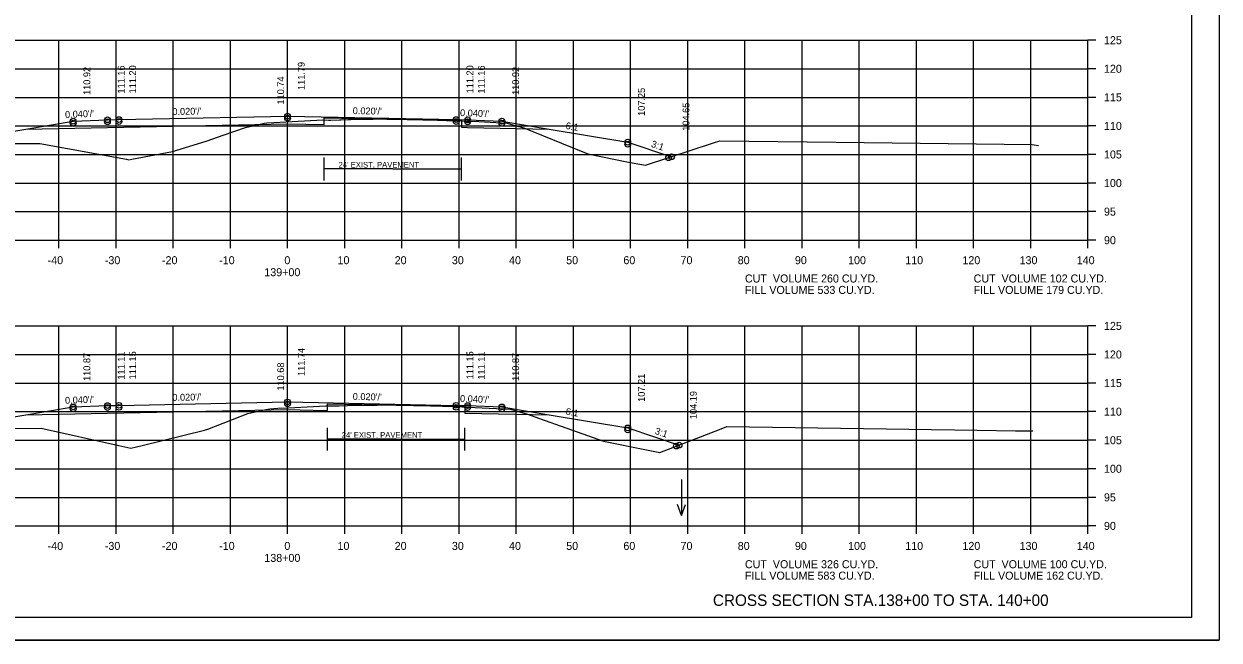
# Model space of a CAD drawing. Extents: x 1175611 to 1176402, y -433344 to -416213.
# Drawn here: x 1175734.9 to 1175943.9, y -430143.5 to -430035.6 of the extents above; entities that cross this region are included whole.
import ezdxf

# ---------------------------------------------------------------- set-up
doc = ezdxf.new("R2010")
doc.units = 0
for name, color, linetype in [('Default', 7, 'Continuous'), ('R_Alt Surface', 7, 'Continuous'), ('R_Axis', 7, 'Continuous'), ('R_Axis Annot', 7, 'Continuous'), ('R_Border', 7, 'Continuous'), ('R_Draft', 7, 'Continuous'), ('R_Exist Surface', 7, 'Continuous'), ('R_Fin Surface', 7, 'Continuous'), ('R_Grid', 7, 'Continuous'), ('R_No Plot', 7, 'Continuous'), ('R_Water Annot', 7, 'Continuous'), ('R_Xsect Elev', 7, 'Continuous'), ('R_Xsect Slope', 7, 'Continuous')]:
    doc.layers.add(name, color=color, linetype=linetype)

msp = doc.modelspace()

# ---------------------------------------------------------------- linework, layer by layer
at = {"layer": 'R_Alt Surface'}
for points in [[(1175735.2, -430054.03), (1175749.47, -430053.74), (1175780.97, -430053.11), (1175787.4, -430053.24), (1175787.4, -430052.07), (1175811.4, -430052.55), (1175811.4, -430053.72), (1175812.47, -430053.74), (1175826.75, -430054.03)], [(1175735.2, -430104.04), (1175749.47, -430103.76), (1175780.97, -430103.12), (1175787.65, -430103.26), (1175787.94, -430103.26), (1175787.94, -430102.1), (1175811.95, -430102.58), (1175811.95, -430103.74), (1175826.75, -430104.04)]]:
    msp.add_lwpolyline(points, dxfattribs=at)
at = {"layer": 'R_Axis'}
for p, q in [((1175920.97, -430073.48), (1175920.97, -430038.48)), ((1175922.37, -430038.48), (1175920.97, -430038.48)), ((1175922.37, -430043.48), (1175920.97, -430043.48)), ((1175922.37, -430048.48), (1175920.97, -430048.48)), ((1175922.37, -430053.48), (1175920.97, -430053.48)), ((1175922.37, -430058.48), (1175920.97, -430058.48)), ((1175922.37, -430063.48), (1175920.97, -430063.48)), ((1175922.37, -430068.48), (1175920.97, -430068.48)), ((1175640.97, -430073.48), (1175920.97, -430073.48)), ((1175740.97, -430074.88), (1175740.97, -430073.48)), ((1175750.97, -430074.88), (1175750.97, -430073.48)), ((1175760.97, -430074.88), (1175760.97, -430073.48)), ((1175770.97, -430074.88), (1175770.97, -430073.48)), ((1175780.97, -430074.88), (1175780.97, -430073.48)), ((1175790.97, -430074.88), (1175790.97, -430073.48)), ((1175800.97, -430074.88), (1175800.97, -430073.48)), ((1175810.97, -430074.88), (1175810.97, -430073.48)), ((1175820.97, -430074.88), (1175820.97, -430073.48)), ((1175830.97, -430074.88), (1175830.97, -430073.48)), ((1175840.97, -430074.88), (1175840.97, -430073.48)), ((1175850.97, -430074.88), (1175850.97, -430073.48)), ((1175860.97, -430074.88), (1175860.97, -430073.48)), ((1175870.97, -430074.88), (1175870.97, -430073.48)), ((1175880.97, -430074.88), (1175880.97, -430073.48)), ((1175890.97, -430074.88), (1175890.97, -430073.48)), ((1175900.97, -430074.88), (1175900.97, -430073.48)), ((1175910.97, -430074.88), (1175910.97, -430073.48)), ((1175920.97, -430074.88), (1175920.97, -430073.48)), ((1175922.37, -430073.48), (1175920.97, -430073.48)), ((1175920.97, -430123.48), (1175920.97, -430088.48)), ((1175922.37, -430088.48), (1175920.97, -430088.48)), ((1175922.37, -430093.48), (1175920.97, -430093.48)), ((1175922.37, -430098.48), (1175920.97, -430098.48)), ((1175922.37, -430103.48), (1175920.97, -430103.48)), ((1175922.37, -430108.48), (1175920.97, -430108.48)), ((1175922.37, -430113.48), (1175920.97, -430113.48)), ((1175922.37, -430118.48), (1175920.97, -430118.48)), ((1175640.97, -430123.48), (1175920.97, -430123.48)), ((1175740.97, -430124.88), (1175740.97, -430123.48)), ((1175750.97, -430124.88), (1175750.97, -430123.48)), ((1175760.97, -430124.88), (1175760.97, -430123.48)), ((1175770.97, -430124.88), (1175770.97, -430123.48)), ((1175780.97, -430124.88), (1175780.97, -430123.48)), ((1175790.97, -430124.88), (1175790.97, -430123.48)), ((1175800.97, -430124.88), (1175800.97, -430123.48)), ((1175810.97, -430124.88), (1175810.97, -430123.48)), ((1175820.97, -430124.88), (1175820.97, -430123.48)), ((1175830.97, -430124.88), (1175830.97, -430123.48)), ((1175840.97, -430124.88), (1175840.97, -430123.48)), ((1175850.97, -430124.88), (1175850.97, -430123.48)), ((1175860.97, -430124.88), (1175860.97, -430123.48)), ((1175870.97, -430124.88), (1175870.97, -430123.48)), ((1175880.97, -430124.88), (1175880.97, -430123.48)), ((1175890.97, -430124.88), (1175890.97, -430123.48)), ((1175900.97, -430124.88), (1175900.97, -430123.48)), ((1175910.97, -430124.88), (1175910.97, -430123.48)), ((1175920.97, -430124.88), (1175920.97, -430123.48)), ((1175922.37, -430123.48), (1175920.97, -430123.48))]:
    msp.add_line(p, q, dxfattribs=at)
at = {"layer": 'R_Border'}
for q in [(1175939.15, -429934.02), (1175622.97, -430139.48)]:
    msp.add_line((1175939.15, -430139.48), q, dxfattribs=at)
at = {"layer": 'R_Draft'}
for p, q in [((1175799.4, -430061.01), (1175787.4, -430061.01)), ((1175799.4, -430061.01), (1175811.4, -430061.01)), ((1175799.94, -430108.29), (1175787.94, -430108.29)), ((1175799.94, -430108.29), (1175811.95, -430108.29))]:
    msp.add_line(p, q, dxfattribs=at)
for points in [[(1175787.4, -430063.01), (1175787.4, -430059.01)], [(1175811.4, -430063.01), (1175811.4, -430059.01)], [(1175787.94, -430110.29), (1175787.94, -430106.29)], [(1175811.95, -430110.29), (1175811.95, -430106.29)]]:
    msp.add_lwpolyline(points, dxfattribs=at)
at = {"layer": 'R_Exist Surface'}
for points in [[(1175731.19, -430056.55), (1175737.66, -430056.53), (1175752.83, -430059.31), (1175753.22, -430059.39), (1175753.71, -430059.29), (1175760.87, -430057.93), (1175765.22, -430056.64), (1175766.91, -430056.09), (1175769.72, -430055.12), (1175773.63, -430053.76), (1175776.17, -430053.18), (1175776.88, -430053.02), (1175777.36, -430052.92), (1175778.55, -430052.86), (1175779.64, -430052.8), (1175787.14, -430052.43), (1175788.13, -430052.47), (1175788.35, -430052.48), (1175788.57, -430052.47), (1175790.08, -430052.42), (1175790.27, -430052.41), (1175791.62, -430052.38), (1175792.06, -430052.37), (1175795.61, -430052.32), (1175795.95, -430052.31), (1175796.96, -430052.26), (1175797.15, -430052.26), (1175798.33, -430052.27), (1175798.51, -430052.28), (1175799.87, -430052.3), (1175800.18, -430052.3), (1175801.87, -430052.35), (1175802.24, -430052.36), (1175804.61, -430052.4), (1175805.55, -430052.42), (1175808.78, -430052.51), (1175809.75, -430052.53), (1175809.87, -430052.53), (1175814.4, -430052.73), (1175819.4, -430052.97), (1175820.95, -430053.44), (1175822.29, -430053.83), (1175828.87, -430056.49), (1175833.48, -430058.35), (1175840.62, -430059.8), (1175843.6, -430060.37), (1175855.47, -430056.44), (1175856.58, -430056.09), (1175876.95, -430056.33), (1175911.23, -430056.75), (1175911.58, -430056.79), (1175912.33, -430056.91)], [(1175726.19, -430106.47), (1175737.86, -430106.39), (1175751.45, -430109.41), (1175753.55, -430109.87), (1175755.53, -430109.41), (1175766.47, -430106.75), (1175767.05, -430106.52), (1175774.03, -430103.8), (1175777.18, -430103.13), (1175777.87, -430102.97), (1175779.29, -430102.9), (1175781.15, -430102.8), (1175787.65, -430102.44), (1175788.32, -430102.46), (1175789.13, -430102.48), (1175790.01, -430102.45), (1175791.44, -430102.41), (1175794.27, -430102.36), (1175796.63, -430102.32), (1175797.31, -430102.3), (1175798.03, -430102.27), (1175798.54, -430102.28), (1175799.02, -430102.3), (1175800.15, -430102.32), (1175801.23, -430102.35), (1175804.21, -430102.41), (1175807.03, -430102.47), (1175808.09, -430102.5), (1175809.43, -430102.54), (1175810, -430102.55), (1175810.41, -430102.56), (1175813.8, -430102.73), (1175819.95, -430103.05), (1175821.16, -430103.4), (1175822.95, -430103.9), (1175825.04, -430104.66), (1175836.24, -430108.66), (1175843.73, -430110.16), (1175846.1, -430110.63), (1175856.51, -430106.58), (1175857.79, -430106.1), (1175901.61, -430106.75), (1175908.31, -430106.83), (1175908.71, -430106.83), (1175911.32, -430106.83)]]:
    msp.add_lwpolyline(points, dxfattribs=at)
at = {"layer": 'R_Fin Surface'}
for points in [[(1175694.36, -430056.6), (1175707.49, -430060.98), (1175721.47, -430056.32), (1175735.2, -430054.03), (1175743.47, -430052.65), (1175749.47, -430052.41), (1175751.47, -430052.37), (1175780.97, -430051.78), (1175810.47, -430052.37), (1175812.47, -430052.41), (1175818.47, -430052.65), (1175826.75, -430054.03), (1175840.47, -430056.32), (1175848.14, -430058.87)], [(1175694.36, -430056.6), (1175707.49, -430060.98), (1175721.47, -430056.32), (1175735.2, -430054.03), (1175743.47, -430052.65), (1175749.47, -430052.41), (1175751.47, -430052.37), (1175780.97, -430051.78), (1175810.47, -430052.37), (1175812.47, -430052.41), (1175818.47, -430052.65), (1175826.75, -430054.03), (1175840.47, -430056.32), (1175848.14, -430058.87)], [(1175690.65, -430106.73), (1175705.46, -430111.67), (1175721.47, -430106.33), (1175735.2, -430104.04), (1175743.47, -430102.66), (1175749.47, -430102.42), (1175751.47, -430102.38), (1175780.97, -430101.79), (1175810.47, -430102.38), (1175812.47, -430102.42), (1175818.47, -430102.66), (1175826.75, -430104.04), (1175840.47, -430106.33), (1175849.46, -430109.33)], [(1175690.65, -430106.73), (1175705.46, -430111.67), (1175721.47, -430106.33), (1175735.2, -430104.04), (1175743.47, -430102.66), (1175749.47, -430102.42), (1175751.47, -430102.38), (1175780.97, -430101.79), (1175810.47, -430102.38), (1175812.47, -430102.42), (1175818.47, -430102.66), (1175826.75, -430104.04), (1175840.47, -430106.33), (1175849.46, -430109.33)]]:
    msp.add_lwpolyline(points, dxfattribs=at)
at = {"layer": 'R_Grid'}
for p, q in [((1175640.97, -430038.48), (1175920.97, -430038.48)), ((1175740.97, -430073.48), (1175740.97, -430038.48)), ((1175750.97, -430073.48), (1175750.97, -430038.48)), ((1175760.97, -430073.48), (1175760.97, -430038.48)), ((1175770.97, -430073.48), (1175770.97, -430038.48)), ((1175780.97, -430073.48), (1175780.97, -430038.48)), ((1175790.97, -430073.48), (1175790.97, -430038.48)), ((1175800.97, -430073.48), (1175800.97, -430038.48)), ((1175810.97, -430073.48), (1175810.97, -430038.48)), ((1175820.97, -430073.48), (1175820.97, -430038.48)), ((1175830.97, -430073.48), (1175830.97, -430038.48)), ((1175840.97, -430073.48), (1175840.97, -430038.48)), ((1175850.97, -430073.48), (1175850.97, -430038.48)), ((1175860.97, -430073.48), (1175860.97, -430038.48)), ((1175870.97, -430073.48), (1175870.97, -430038.48)), ((1175880.97, -430073.48), (1175880.97, -430038.48)), ((1175890.97, -430073.48), (1175890.97, -430038.48)), ((1175900.97, -430073.48), (1175900.97, -430038.48)), ((1175910.97, -430073.48), (1175910.97, -430038.48)), ((1175920.97, -430073.48), (1175920.97, -430038.48)), ((1175640.97, -430043.48), (1175920.97, -430043.48)), ((1175640.97, -430048.48), (1175920.97, -430048.48)), ((1175640.97, -430053.48), (1175920.97, -430053.48)), ((1175640.97, -430058.48), (1175920.97, -430058.48)), ((1175640.97, -430063.48), (1175920.97, -430063.48)), ((1175640.97, -430068.48), (1175920.97, -430068.48)), ((1175640.97, -430073.48), (1175920.97, -430073.48)), ((1175640.97, -430088.48), (1175920.97, -430088.48)), ((1175740.97, -430123.48), (1175740.97, -430088.48)), ((1175750.97, -430123.48), (1175750.97, -430088.48)), ((1175760.97, -430123.48), (1175760.97, -430088.48)), ((1175770.97, -430123.48), (1175770.97, -430088.48)), ((1175780.97, -430123.48), (1175780.97, -430088.48)), ((1175790.97, -430123.48), (1175790.97, -430088.48)), ((1175800.97, -430123.48), (1175800.97, -430088.48)), ((1175810.97, -430123.48), (1175810.97, -430088.48)), ((1175820.97, -430123.48), (1175820.97, -430088.48)), ((1175830.97, -430123.48), (1175830.97, -430088.48)), ((1175840.97, -430123.48), (1175840.97, -430088.48)), ((1175850.97, -430123.48), (1175850.97, -430088.48)), ((1175860.97, -430123.48), (1175860.97, -430088.48)), ((1175870.97, -430123.48), (1175870.97, -430088.48)), ((1175880.97, -430123.48), (1175880.97, -430088.48)), ((1175890.97, -430123.48), (1175890.97, -430088.48)), ((1175900.97, -430123.48), (1175900.97, -430088.48)), ((1175910.97, -430123.48), (1175910.97, -430088.48)), ((1175920.97, -430123.48), (1175920.97, -430088.48)), ((1175640.97, -430093.48), (1175920.97, -430093.48)), ((1175640.97, -430098.48), (1175920.97, -430098.48)), ((1175640.97, -430103.48), (1175920.97, -430103.48)), ((1175640.97, -430108.48), (1175920.97, -430108.48)), ((1175640.97, -430113.48), (1175920.97, -430113.48)), ((1175640.97, -430118.48), (1175920.97, -430118.48)), ((1175640.97, -430123.48), (1175920.97, -430123.48))]:
    msp.add_line(p, q, dxfattribs=at)
at = {"layer": 'R_No Plot'}
msp.add_line((1175610.57, -430143.46), (1175943.91, -430143.46), dxfattribs=at)
msp.add_lwpolyline([(1175610.57, -429930.13), (1175943.91, -429930.13), (1175943.91, -430143.46), (1175610.57, -430143.46)], close=True, dxfattribs=at)
for centre in [(1175743.47, -430052.65), (1175749.47, -430052.41), (1175749.47, -430052.76), (1175751.47, -430052.37), (1175751.47, -430052.72), (1175780.97, -430051.78), (1175780.97, -430052.13), (1175810.47, -430052.37), (1175810.47, -430052.72), (1175812.47, -430052.41), (1175812.47, -430052.76), (1175818.47, -430052.65), (1175743.47, -430053), (1175818.47, -430053), (1175840.47, -430056.32), (1175840.47, -430056.67), (1175847.61, -430059.05), (1175848.14, -430058.87), (1175848.14, -430058.87), (1175743.47, -430102.66), (1175749.47, -430102.42), (1175749.47, -430102.77), (1175751.47, -430102.38), (1175751.47, -430102.73), (1175780.97, -430101.79), (1175780.97, -430102.14), (1175810.47, -430102.38), (1175810.47, -430102.73), (1175812.47, -430102.42), (1175812.47, -430102.77), (1175818.47, -430102.66), (1175743.47, -430103.01), (1175818.47, -430103.01), (1175840.47, -430106.33), (1175840.47, -430106.68), (1175848.97, -430109.51), (1175849.46, -430109.33), (1175849.46, -430109.33)]:
    msp.add_circle(centre, 0.5, dxfattribs=at)
at = {"layer": 'R_Water Annot'}
for p, q in [((1175849.85, -430115.35), (1175849.85, -430121.63)), ((1175849.85, -430121.63), (1175849.15, -430119.71)), ((1175849.85, -430121.63), (1175850.55, -430119.71))]:
    msp.add_line(p, q, dxfattribs=at)

# ---------------------------------------------------------------- texts
at = {"layer": 'Default'}
for s, p in [('CUT  VOLUME 260 CU.YD.', (1175860.97, -430080.88)), ('CUT  VOLUME 102 CU.YD.', (1175900.97, -430080.88)), ('FILL VOLUME 533 CU.YD.', (1175860.97, -430082.88)), ('FILL VOLUME 179 CU.YD.', (1175900.97, -430082.88)), ('CUT  VOLUME 326 CU.YD.', (1175860.97, -430130.88)), ('CUT  VOLUME 100 CU.YD.', (1175900.97, -430130.88)), ('FILL VOLUME 583 CU.YD.', (1175860.97, -430132.88)), ('FILL VOLUME 162 CU.YD.', (1175900.97, -430132.88))]:
    msp.add_text(s, height=1.4, dxfattribs=at).set_placement(p)
at = {"layer": 'R_Axis Annot'}
for s, p in [('125', (1175923.77, -430039.18)), ('120', (1175923.77, -430044.18)), ('115', (1175923.77, -430049.18)), ('110', (1175923.77, -430054.18)), ('105', (1175923.77, -430059.18)), ('100', (1175923.77, -430064.18)), ('95', (1175923.77, -430069.18)), ('90', (1175923.77, -430074.18)), ('-40', (1175739.01, -430077.68)), ('-30', (1175749.01, -430077.68)), ('-20', (1175759.01, -430077.68)), ('-10', (1175769.01, -430077.68)), ('0', (1175780.41, -430077.68)), ('10', (1175789.71, -430077.68)), ('20', (1175799.71, -430077.68)), ('30', (1175809.71, -430077.68)), ('40', (1175819.71, -430077.68)), ('50', (1175829.71, -430077.68)), ('60', (1175839.71, -430077.68)), ('70', (1175849.71, -430077.68)), ('80', (1175859.71, -430077.68)), ('90', (1175869.71, -430077.68)), ('100', (1175879.01, -430077.68)), ('110', (1175889.01, -430077.68)), ('120', (1175899.01, -430077.68)), ('130', (1175909.01, -430077.68)), ('140', (1175919.01, -430077.68)), ('139+00', (1175776.91, -430079.78)), ('125', (1175923.77, -430089.18)), ('120', (1175923.77, -430094.18)), ('115', (1175923.77, -430099.18)), ('110', (1175923.77, -430104.18)), ('105', (1175923.77, -430109.18)), ('100', (1175923.77, -430114.18)), ('95', (1175923.77, -430119.18)), ('90', (1175923.77, -430124.18)), ('-40', (1175739.01, -430127.68)), ('-30', (1175749.01, -430127.68)), ('-20', (1175759.01, -430127.68)), ('-10', (1175769.01, -430127.68)), ('0', (1175780.41, -430127.68)), ('10', (1175789.71, -430127.68)), ('20', (1175799.71, -430127.68)), ('30', (1175809.71, -430127.68)), ('40', (1175819.71, -430127.68)), ('50', (1175829.71, -430127.68)), ('60', (1175839.71, -430127.68)), ('70', (1175849.71, -430127.68)), ('80', (1175859.71, -430127.68)), ('90', (1175869.71, -430127.68)), ('100', (1175879.01, -430127.68)), ('110', (1175889.01, -430127.68)), ('120', (1175899.01, -430127.68)), ('130', (1175909.01, -430127.68)), ('140', (1175919.01, -430127.68)), ('138+00', (1175776.91, -430129.78))]:
    msp.add_text(s, height=1.4, dxfattribs=at).set_placement(p)
at = {"layer": 'R_Draft'}
for s, height, p in [("24' EXIST. PAVEMENT", 1, (1175789.9, -430060.78)), ("24' EXIST. PAVEMENT", 1, (1175790.45, -430108.06)), ('CROSS SECTION STA.138+00 TO STA. 140+00', 2, (1175855.37, -430137.48))]:
    msp.add_text(s, height=height, dxfattribs=at).set_placement(p)
at = {"layer": 'R_Xsect Elev'}
for s, p in [('110.92', (1175746.47, -430048.06)), ('111.16', (1175752.47, -430047.82)), ('111.20', (1175754.47, -430047.78)), ('111.79', (1175783.97, -430047.19)), ('111.20', (1175813.47, -430047.78)), ('111.16', (1175815.47, -430047.82)), ('110.92', (1175821.47, -430048.06)), ('110.74', (1175780.37, -430049.74)), ('107.25', (1175843.47, -430051.73)), ('104.65', (1175851.26, -430054.33)), ('110.87', (1175746.47, -430098.11)), ('111.11', (1175752.47, -430097.87)), ('111.15', (1175754.47, -430097.83)), ('111.74', (1175783.97, -430097.24)), ('111.15', (1175813.47, -430097.83)), ('111.11', (1175815.47, -430097.87)), ('110.87', (1175821.47, -430098.11)), ('110.68', (1175780.37, -430099.8)), ('107.21', (1175843.47, -430101.77)), ('104.19', (1175852.54, -430104.79))]:
    msp.add_text(s, height=1.2, rotation=90, dxfattribs=at).set_placement(p)
at = {"layer": 'R_Xsect Slope'}
for s, rotation, p in [("0.020'/'", 1.1458, (1175760.83, -430051.58)), ("0.020'/'", 358.8542, (1175792.36, -430051.41)), ("0.040'/'", 2.2906, (1175742.07, -430052.1)), ("0.040'/'", 357.7094, (1175811.12, -430051.75)), ('6:1', 350.5377, (1175829.55, -430053.99)), ('3:1', 341.5651, (1175844.46, -430057.12)), ("0.020'/'", 1.1458, (1175760.83, -430101.6)), ("0.020'/'", 358.8542, (1175792.36, -430101.42)), ("0.040'/'", 2.2906, (1175742.07, -430102.12)), ("0.040'/'", 357.7094, (1175811.12, -430101.77)), ('6:1', 350.5377, (1175829.55, -430104)), ('3:1', 341.5651, (1175845.12, -430107.35))]:
    msp.add_text(s, height=1.2, rotation=rotation, dxfattribs=at).set_placement(p)

doc.saveas('drawing.dxf')
